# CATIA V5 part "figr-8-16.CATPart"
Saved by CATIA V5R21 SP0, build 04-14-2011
Part number: Part1
Bounding box of the stored display mesh (mm): x -55.501 to 55.501, y -84.223 to 84.223, z 0 to 81
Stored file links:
  D:\CATIA V5R21 E-RESOURCES\CATIA-V5R21\catia-v5r21-prt\c08-catia-v5r20-prt\c08-catia-v5r21-figr-8-16.CATPart
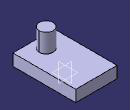
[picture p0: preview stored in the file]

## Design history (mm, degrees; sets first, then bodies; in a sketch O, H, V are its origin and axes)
Body1 (main body)
  Sketch1 on xy-plane, origin (0, 0, 0), H (1, 0, 0), V (0, 1, 0)
    line L1 (-55.501, 84.2232) -> (55.501, 84.2232)
    line L2 (55.501, 84.2232) -> (55.501, -84.2232)
    line L3 (55.501, -84.2232) -> (-55.501, -84.2232)
    line L4 (-55.501, -84.2232) -> (-55.501, 84.2232)
    axis line L5 (55.501, -84.2232) -> (-55.501, 84.2232)
    horizontal: L1 H, L3 H
    vertical: L2 V, L4 V
    midpoint: O L5
  Pad1: profile Sketch1, direction (0, 0, 1), length 31
  Sketch2 on face of Pad1, origin (0, 0, 31), H (1, 0, 0), V (0, 1, 0)
    circle A1 centre (0, -50.4568) radius 18.9426
    point P1 (0, -50.4568)
    coincidence: P1 V
  Pad2: profile Sketch2, direction (0, 0, 1), length 50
